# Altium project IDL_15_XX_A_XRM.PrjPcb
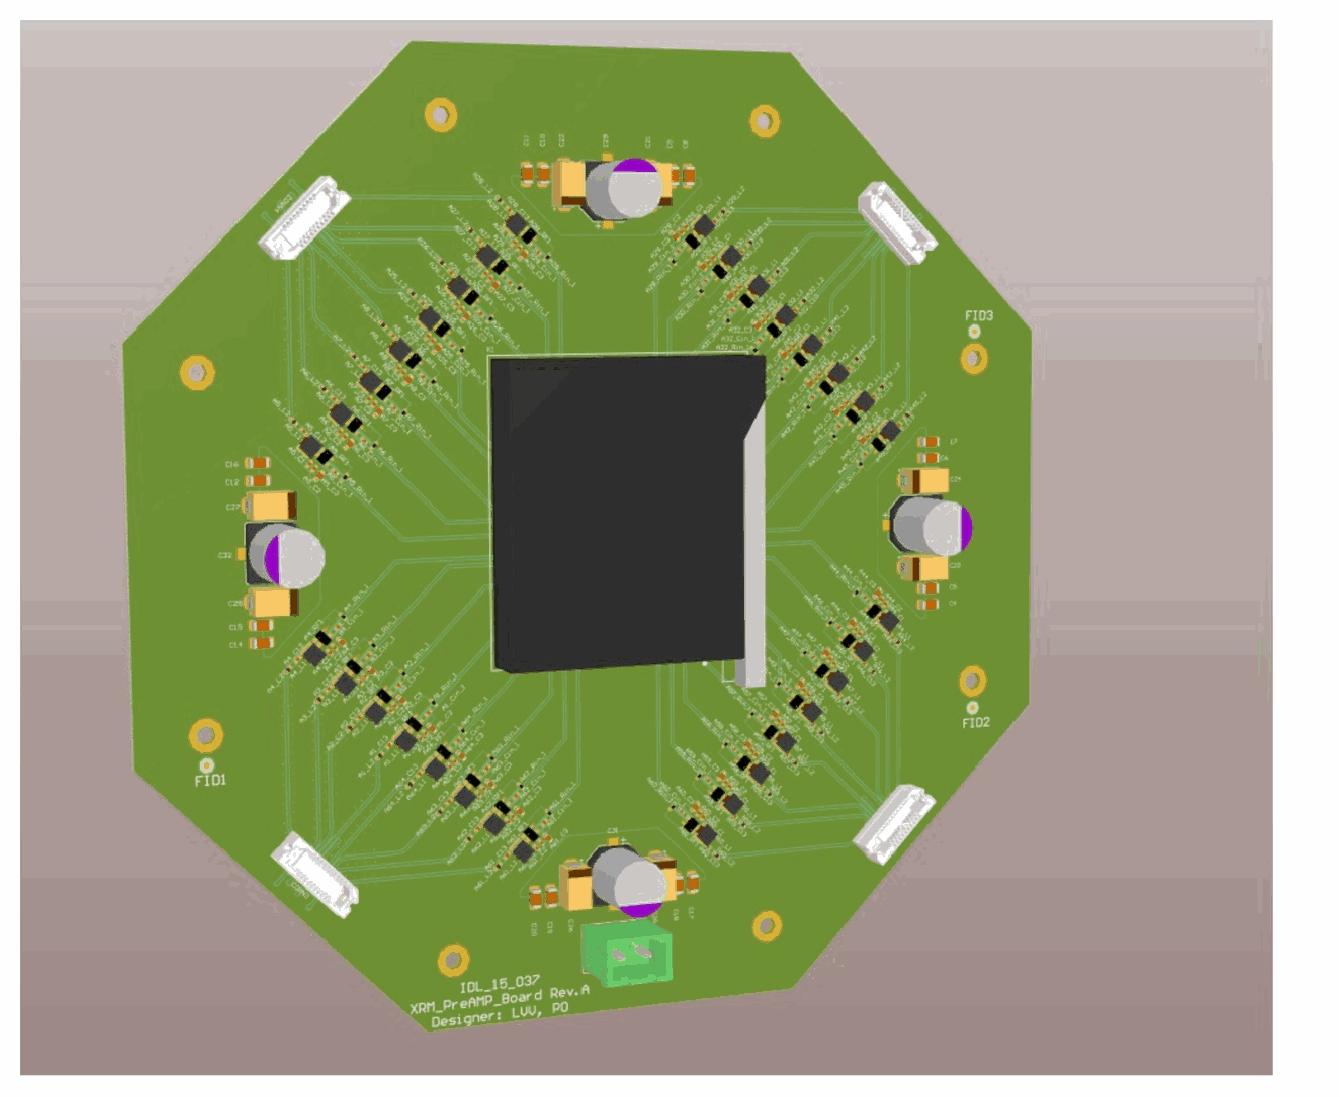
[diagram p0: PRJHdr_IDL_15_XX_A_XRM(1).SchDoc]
RevNum: A; ProjectName1: X-Ray Monitor; IDLnum: IDL_15_037; Drawn_By: Vihtori Virta; Designer: L.V. Virta, P. Orel; BoardName: XRM-Preamp Board; Approved_By: Gary S. Varner
6 sheets, 613 parts. Net scope: hierarchical (ports join the sheet entries above them; power ports are global).
Board file: IDL_15_XX_A_XRM.PcbDoc
Sheets:
  PRJHdr_IDL_15_XX_A_XRM(1).SchDoc
  IDL_15_XX_A_XRM(2).SchDoc
  IDL_15_XX_A_XRM-TOP(1).SchDoc
    A1 = IDL_15_XX_A_XRM(4).SchDoc
    A2 = IDL_15_XX_A_XRM(4).SchDoc
    A3 = IDL_15_XX_A_XRM(4).SchDoc
    A4 = IDL_15_XX_A_XRM(4).SchDoc
    A5 = IDL_15_XX_A_XRM(4).SchDoc
    A6 = IDL_15_XX_A_XRM(4).SchDoc
    A7 = IDL_15_XX_A_XRM(4).SchDoc
    A8 = IDL_15_XX_A_XRM(4).SchDoc
    A9 = IDL_15_XX_A_XRM(4).SchDoc
    A10 = IDL_15_XX_A_XRM(4).SchDoc
    A11 = IDL_15_XX_A_XRM(4).SchDoc
    A12 = IDL_15_XX_A_XRM(4).SchDoc
    A13 = IDL_15_XX_A_XRM(4).SchDoc
    A14 = IDL_15_XX_A_XRM(4).SchDoc
    A15 = IDL_15_XX_A_XRM(4).SchDoc
    A16 = IDL_15_XX_A_XRM(4).SchDoc
    A17 = IDL_15_XX_A_XRM(4).SchDoc
    A18 = IDL_15_XX_A_XRM(4).SchDoc
    A19 = IDL_15_XX_A_XRM(4).SchDoc
    A20 = IDL_15_XX_A_XRM(4).SchDoc
    A21 = IDL_15_XX_A_XRM(4).SchDoc
    A22 = IDL_15_XX_A_XRM(4).SchDoc
    A23 = IDL_15_XX_A_XRM(4).SchDoc
    A24 = IDL_15_XX_A_XRM(4).SchDoc
    A25 = IDL_15_XX_A_XRM(4).SchDoc
    A26 = IDL_15_XX_A_XRM(4).SchDoc
    A27 = IDL_15_XX_A_XRM(4).SchDoc
    A28 = IDL_15_XX_A_XRM(4).SchDoc
    A29 = IDL_15_XX_A_XRM(4).SchDoc
    A30 = IDL_15_XX_A_XRM(4).SchDoc
    A31 = IDL_15_XX_A_XRM(4).SchDoc
    A32 = IDL_15_XX_A_XRM(4).SchDoc
    A33 = IDL_15_XX_A_XRM(4).SchDoc
    A34 = IDL_15_XX_A_XRM(4).SchDoc
    A35 = IDL_15_XX_A_XRM(4).SchDoc
    A36 = IDL_15_XX_A_XRM(4).SchDoc
    A37 = IDL_15_XX_A_XRM(4).SchDoc
    A38 = IDL_15_XX_A_XRM(4).SchDoc
    A39 = IDL_15_XX_A_XRM(4).SchDoc
    A40 = IDL_15_XX_A_XRM(4).SchDoc
    A41 = IDL_15_XX_A_XRM(4).SchDoc
    A42 = IDL_15_XX_A_XRM(4).SchDoc
    A43 = IDL_15_XX_A_XRM(4).SchDoc
    A44 = IDL_15_XX_A_XRM(4).SchDoc
    A45 = IDL_15_XX_A_XRM(4).SchDoc
    A46 = IDL_15_XX_A_XRM(4).SchDoc
    A47 = IDL_15_XX_A_XRM(4).SchDoc
    A48 = IDL_15_XX_A_XRM(4).SchDoc
    A49 = IDL_15_XX_A_XRM(4).SchDoc
    A50 = IDL_15_XX_A_XRM(4).SchDoc
    A51 = IDL_15_XX_A_XRM(4).SchDoc
    A52 = IDL_15_XX_A_XRM(4).SchDoc
    A53 = IDL_15_XX_A_XRM(4).SchDoc
    A54 = IDL_15_XX_A_XRM(4).SchDoc
    A55 = IDL_15_XX_A_XRM(4).SchDoc
    A56 = IDL_15_XX_A_XRM(4).SchDoc
    A57 = IDL_15_XX_A_XRM(4).SchDoc
    A58 = IDL_15_XX_A_XRM(4).SchDoc
    A59 = IDL_15_XX_A_XRM(4).SchDoc
    A60 = IDL_15_XX_A_XRM(4).SchDoc
    A61 = IDL_15_XX_A_XRM(4).SchDoc
    A62 = IDL_15_XX_A_XRM(4).SchDoc
    A63 = IDL_15_XX_A_XRM(4).SchDoc
    A64 = IDL_15_XX_A_XRM(4).SchDoc
    U_IDL_15_XX_A_XRM-20_PIN_CONNECTOR = IDL_15_XX_A_XRM-20_PIN_CONNECTOR.SchDoc
    U_IDL_15_XX_A_XRM(3) = IDL_15_XX_A_XRM(3).SchDoc

## Sheet PRJHdr_IDL_15_XX_A_XRM(1).SchDoc: Document Header
size 401 x 291 mm; DocumentNumber: 1; SheetNumber: 1; SheetTotal: 6; Project_IT-Code: XXXX

## Sheet IDL_15_XX_A_XRM(2).SchDoc: Block Diagram
size 401 x 291 mm; DocumentNumber: 2; SheetNumber: 2; SheetTotal: 6
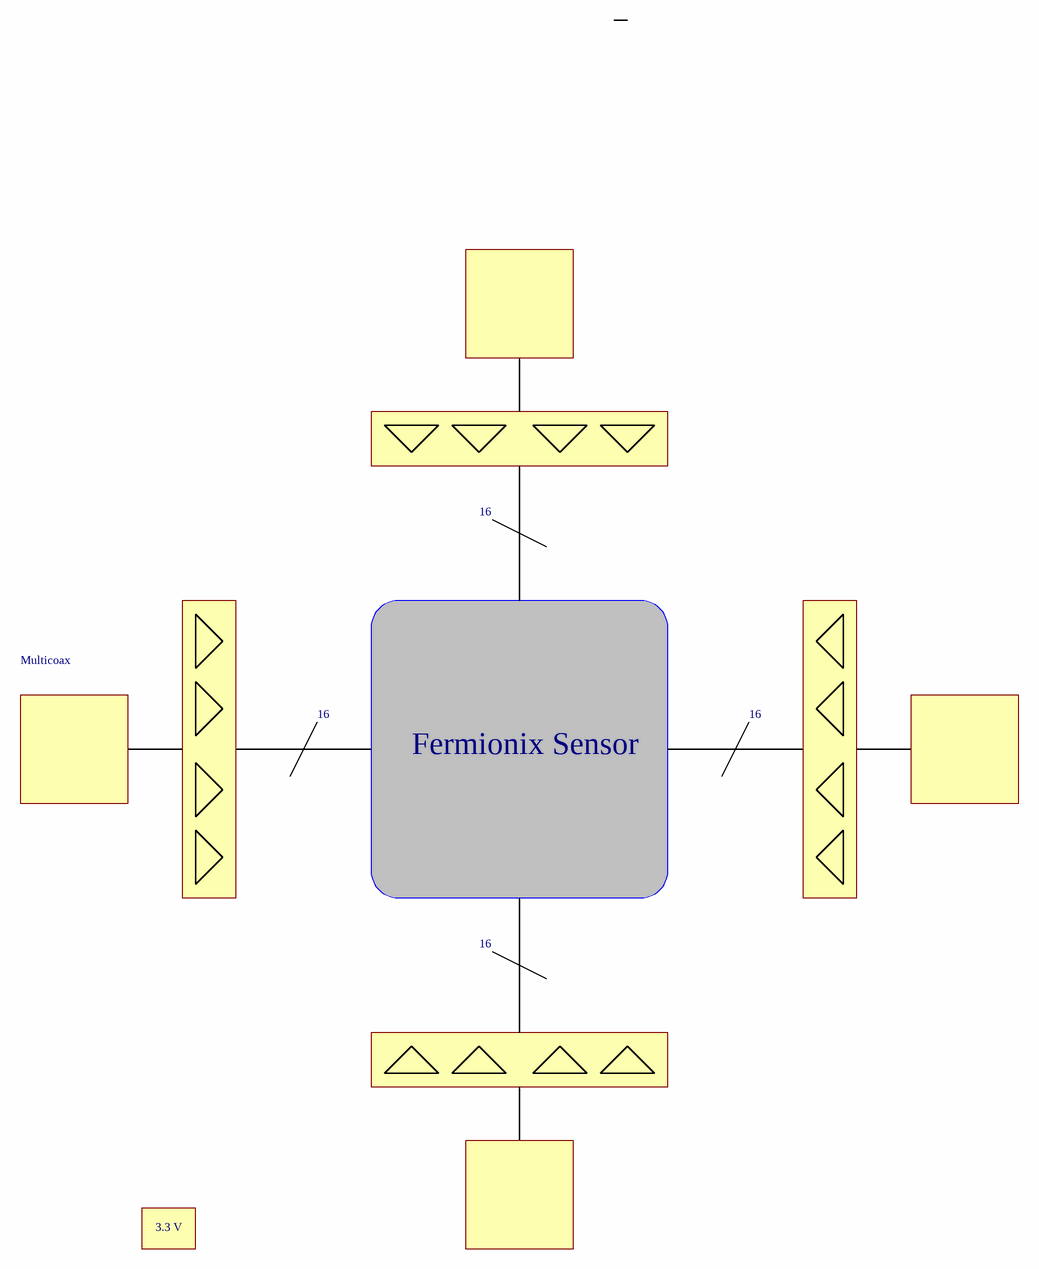
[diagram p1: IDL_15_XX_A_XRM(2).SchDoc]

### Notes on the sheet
- 16
- Multicoax
- Fermionix Sensor
- 3.3 V

## Sheet IDL_15_XX_A_XRM-TOP(1).SchDoc: Schematic - TOP
size 401 x 291 mm; DocumentNumber: 4; SheetNumber: 4; SheetTotal: 6
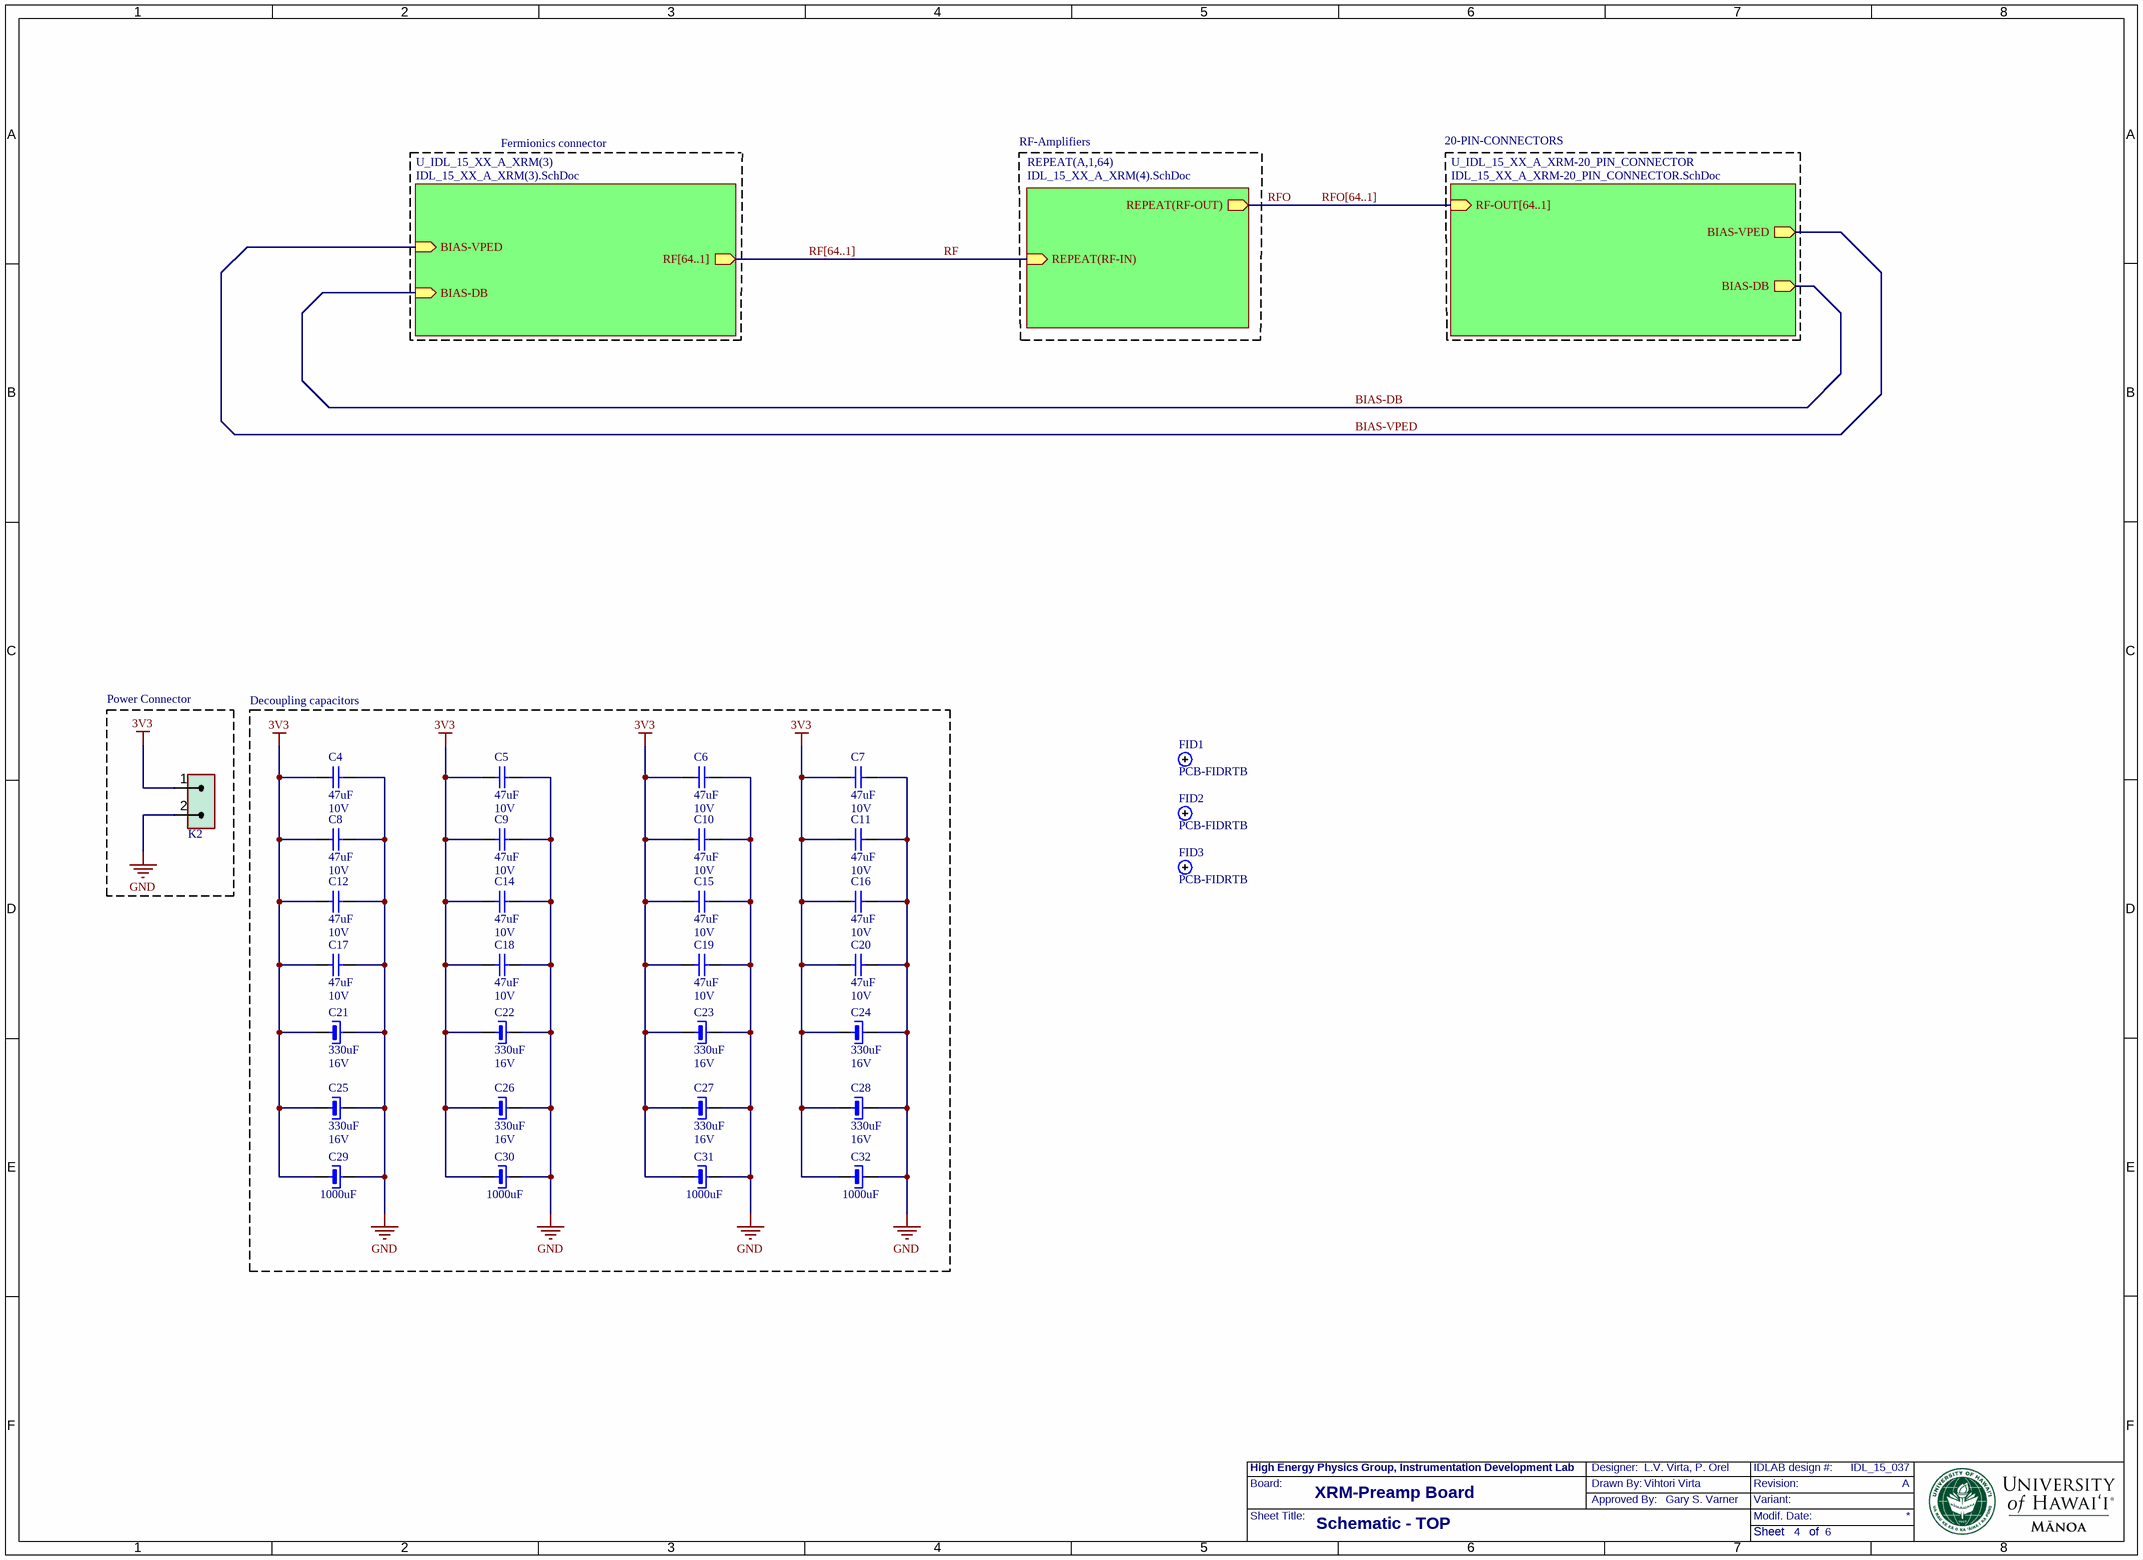
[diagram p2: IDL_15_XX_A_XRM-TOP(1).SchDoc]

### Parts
C4  47uF  Voltage rating: 10V  [CC1206N1R]
C5  47uF  Voltage rating: 10V  [CC1206N1R]
C6  47uF  Voltage rating: 10V  [CC1206N1R]
C7  47uF  Voltage rating: 10V  [CC1206N1R]
C8  47uF  Voltage rating: 10V  [CC1206N1R]
C9  47uF  Voltage rating: 10V  [CC1206N1R]
C10  47uF  Voltage rating: 10V  [CC1206N1R]
C11  47uF  Voltage rating: 10V  [CC1206N1R]
C12  47uF  Voltage rating: 10V  [CC1206N1R]
C14  47uF  Voltage rating: 10V  [CC1206N1R]
C15  47uF  Voltage rating: 10V  [CC1206N1R]
C16  47uF  Voltage rating: 10V  [CC1206N1R]
C17  47uF  Voltage rating: 10V  [CC1206N1R]
C18  47uF  Voltage rating: 10V  [CC1206N1R]
C19  47uF  Voltage rating: 10V  [CC1206N1R]
C20  47uF  Voltage rating: 10V  [CC1206N1R]
C21  330uF  Voltage rating: 16V  [CTC-D7343-43]
C22  330uF  Voltage rating: 16V  [CTC-D7343-43]
C23  330uF  Voltage rating: 16V  [CTC-D7343-43]
C24  330uF  Voltage rating: 16V  [CTC-D7343-43]
C25  330uF  Voltage rating: 16V  [CTC-D7343-43]
C26  330uF  Voltage rating: 16V  [CTC-D7343-43]
C27  330uF  Voltage rating: 16V  [CTC-D7343-43]
C28  330uF  Voltage rating: 16V  [CTC-D7343-43]
C29  1000uF  [CAPPS-D10X12.6]
C30  1000uF  [CAPPS-D10X12.6]
C31  1000uF  [CAPPS-D10X12.6]
C32  1000uF  [CAPPS-D10X12.6]
FID1  PCB-FIDRTB  [FIDRTB50]  (net tie)
FID2  PCB-FIDRTB  [FIDRTB50]  (net tie)
FID3  PCB-FIDRTB  [FIDRTB50]  (net tie)
K2  MSTBA2R5.08V  [CN_PHOENIX_MSTBVA2,5/2-G-5,08]  (value not drawn)

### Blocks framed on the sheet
Power Connector: K2
Decoupling capacitors: C4-C12 C14-C32

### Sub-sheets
REPEAT(A,1,64) = IDL_15_XX_A_XRM(4).SchDoc: REPEAT(RF-OUT) (out), REPEAT(RF-IN) (in)
U_IDL_15_XX_A_XRM(3) = IDL_15_XX_A_XRM(3).SchDoc: RF[64..1] (out), BIAS-VPED (in), BIAS-DB (in)
U_IDL_15_XX_A_XRM-20_PIN_CONNECTOR = IDL_15_XX_A_XRM-20_PIN_CONNECTOR.SchDoc: RF-OUT[64..1] (in), BIAS-VPED, BIAS-DB

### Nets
3V3: C4.1 C5.1 C6.1 C7.1 C8.1 C9.1 C10.1 C11.1 C12.1 C14.1 C15.1 C16.1 C17.1 C18.1 C19.1 C20.1 C21.1 C22.1 C23.1 C24.1 C25.1 C26.1 C27.1 C28.1 C29.1 C30.1 C31.1 C32.1 K2.1
GND: C4.2 C5.2 C6.2 C7.2 C8.2 C9.2 C10.2 C11.2 C12.2 C14.2 C15.2 C16.2 C17.2 C18.2 C19.2 C20.2 C21.2 C22.2 C23.2 C24.2 C25.2 C26.2 C27.2 C28.2 C29.2 C30.2 C31.2 C32.2 K2.2
BIAS-DB: sheet U_IDL_15_XX_A_XRM-20_PIN_CONNECTOR/BIAS-DB, sheet U_IDL_15_XX_A_XRM(3)/BIAS-DB
BIAS-VPED: sheet U_IDL_15_XX_A_XRM-20_PIN_CONNECTOR/BIAS-VPED, sheet U_IDL_15_XX_A_XRM(3)/BIAS-VPED  [project net BIAS-DB]

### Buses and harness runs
bus RF[64..1] = sheet U_IDL_15_XX_A_XRM(3)/RF[64..1]
bus RFO[64..1] = sheet U_IDL_15_XX_A_XRM-20_PIN_CONNECTOR/RF-OUT[64..1]

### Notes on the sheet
- Fermionics connector
- RF-Amplifiers
- 20-PIN-CONNECTORS

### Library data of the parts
C4-C12 C14-C20 = CAPCC1206_47U_10VX5R: Capacitor chip ceramic 1206 10V X5R; Manufacturer: Murata; Manufacturer No: GRM31CR61A476ME15L; Tech: SMDR
C21-C28 = CAPT7343_330U_16V: Capacitor tantal smd 7343-43 16V 50mResr; Manufacturer: Kemet; Manufacturer No: T521X337M016ATE050; Tech: SMDR
C29-C32 = CAPPS1000U-16V80mR: Capacitor electrolitic SMD 10x10x8mm 16V 80mR; Manufacturer: Panasonic; Manufacturer No: EEE-FT1C102AP; Tech: SMDR
FID1-FID3 = PCB-FIDRTB: Fiducial top & bottom round open mask; Sort: 800; Tech: MECH
K2 = CN_MSTBA2R5.08V: Combicon header 2 pin vertical closed R5.08mm 12A 300V; Manufacturer: Phoenix Contact; Manufacturer No: 1755736; Tech: THDW

## Sheet IDL_15_XX_A_XRM(4).SchDoc: Schematic - Amplifier connections
size 401 x 291 mm; DocumentNumber: 5; SheetNumber: 5; SheetTotal: 6
Used 64 times, as channels A1, A2, A3, A4, A5, A6, A7, A8, A9, A10, A11, A12, A13, A14, A15, A16, A17, A18, A19, A20, A21, A22, A23, A24, A25, A26, A27, A28, A29, A30, A31, A32, A33, A34, A35, A36, A37, A38, A39, A40, A41, A42, A43, A44, A45, A46, A47, A48, A49, A50, A51, A52, A53, A54, A55, A56, A57, A58, A59, A60, A61, A62, A63, A64. Parts and nets are listed once, with the designators drawn on the sheet.
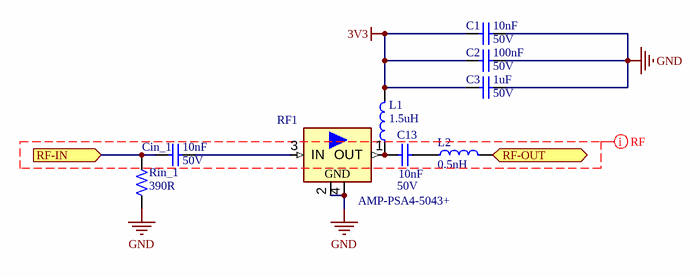
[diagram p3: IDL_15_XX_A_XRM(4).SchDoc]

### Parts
C1  10nF  Voltage rating: 50V  [CC0402N1R]
C2  100nF  Voltage rating: 50V  [CC0402N1R]
C3  1uF  Voltage rating: 50V  [CC0603RF1R]
C13  10nF  Voltage rating: 50V  [CC0402N1R]
Cin_1  10nF  Voltage rating: 50V  [CC0402N1R]
L1  1.5uH  [LC1008CS]
L2  0.5nH  [LC0402N1R]
RF1  AMP-PSA4-5043+  [MMM1362]
Rin_1  390R  [RC0402N1R]

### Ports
RF-IN (in), RF-OUT (out)

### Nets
3V3: C1.1 C2.1 C3.1 L1.2
GND: C1.2 C2.2 C3.2 RF1.2(GND) RF1.4(GND) Rin_1.1
RF-IN: Cin_1.1 Rin_1.2 ; port RF-IN
RF-OUT: L2.2 ; port RF-OUT
NetC13_1: C13.1 L1.1 RF1.1(OUT)
NetC13_2: C13.2 L2.1
NetCin_1_2: Cin_1.2 RF1.3(IN)

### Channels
A1: designators C1=A1_C1 C2=A1_C2 C3=A1_C3 C13=A1_C13 Cin_1=A1_Cin_1 L1=A1_L1 L2=A1_L2 RF1=A1_RF1 Rin_1=A1_Rin_1; ports RF-IN=RF1 RF-OUT=RF-OUT1
A2: designators C1=A2_C1 C2=A2_C2 C3=A2_C3 C13=A2_C13 Cin_1=A2_Cin_1 L1=A2_L1 L2=A2_L2 RF1=A2_RF1 Rin_1=A2_Rin_1; ports RF-IN=RF2 RF-OUT=RF-OUT2
A3: designators C1=A3_C1 C2=A3_C2 C3=A3_C3 C13=A3_C13 Cin_1=A3_Cin_1 L1=A3_L1 L2=A3_L2 RF1=A3_RF1 Rin_1=A3_Rin_1; ports RF-IN=RF3 RF-OUT=RF-OUT3
A4: designators C1=A4_C1 C2=A4_C2 C3=A4_C3 C13=A4_C13 Cin_1=A4_Cin_1 L1=A4_L1 L2=A4_L2 RF1=A4_RF1 Rin_1=A4_Rin_1; ports RF-IN=RF4 RF-OUT=RF-OUT4
A5: designators C1=A5_C1 C2=A5_C2 C3=A5_C3 C13=A5_C13 Cin_1=A5_Cin_1 L1=A5_L1 L2=A5_L2 RF1=A5_RF1 Rin_1=A5_Rin_1; ports RF-IN=RF5 RF-OUT=RF-OUT5
A6: designators C1=A6_C1 C2=A6_C2 C3=A6_C3 C13=A6_C13 Cin_1=A6_Cin_1 L1=A6_L1 L2=A6_L2 RF1=A6_RF1 Rin_1=A6_Rin_1; ports RF-IN=RF6 RF-OUT=RF-OUT6
A7: designators C1=A7_C1 C2=A7_C2 C3=A7_C3 C13=A7_C13 Cin_1=A7_Cin_1 L1=A7_L1 L2=A7_L2 RF1=A7_RF1 Rin_1=A7_Rin_1; ports RF-IN=RF7 RF-OUT=RF-OUT7
A8: designators C1=A8_C1 C2=A8_C2 C3=A8_C3 C13=A8_C13 Cin_1=A8_Cin_1 L1=A8_L1 L2=A8_L2 RF1=A8_RF1 Rin_1=A8_Rin_1; ports RF-IN=RF8 RF-OUT=RF-OUT8
A9: designators C1=A9_C1 C2=A9_C2 C3=A9_C3 C13=A9_C13 Cin_1=A9_Cin_1 L1=A9_L1 L2=A9_L2 RF1=A9_RF1 Rin_1=A9_Rin_1; ports RF-IN=RF9 RF-OUT=RF-OUT9
A10: designators C1=A10_C1 C2=A10_C2 C3=A10_C3 C13=A10_C13 Cin_1=A10_Cin_1 L1=A10_L1 L2=A10_L2 RF1=A10_RF1 Rin_1=A10_Rin_1; ports RF-IN=RF10 RF-OUT=RF-OUT10
A11: designators C1=A11_C1 C2=A11_C2 C3=A11_C3 C13=A11_C13 Cin_1=A11_Cin_1 L1=A11_L1 L2=A11_L2 RF1=A11_RF1 Rin_1=A11_Rin_1; ports RF-IN=RF11 RF-OUT=RF-OUT11
A12: designators C1=A12_C1 C2=A12_C2 C3=A12_C3 C13=A12_C13 Cin_1=A12_Cin_1 L1=A12_L1 L2=A12_L2 RF1=A12_RF1 Rin_1=A12_Rin_1; ports RF-IN=RF12 RF-OUT=RF-OUT12
A13: designators C1=A13_C1 C2=A13_C2 C3=A13_C3 C13=A13_C13 Cin_1=A13_Cin_1 L1=A13_L1 L2=A13_L2 RF1=A13_RF1 Rin_1=A13_Rin_1; ports RF-IN=RF13 RF-OUT=RF-OUT13
A14: designators C1=A14_C1 C2=A14_C2 C3=A14_C3 C13=A14_C13 Cin_1=A14_Cin_1 L1=A14_L1 L2=A14_L2 RF1=A14_RF1 Rin_1=A14_Rin_1; ports RF-IN=RF14 RF-OUT=RF-OUT14
A15: designators C1=A15_C1 C2=A15_C2 C3=A15_C3 C13=A15_C13 Cin_1=A15_Cin_1 L1=A15_L1 L2=A15_L2 RF1=A15_RF1 Rin_1=A15_Rin_1; ports RF-IN=RF15 RF-OUT=RF-OUT15
A16: designators C1=A16_C1 C2=A16_C2 C3=A16_C3 C13=A16_C13 Cin_1=A16_Cin_1 L1=A16_L1 L2=A16_L2 RF1=A16_RF1 Rin_1=A16_Rin_1; ports RF-IN=RF16 RF-OUT=RF-OUT16
A17: designators C1=A17_C1 C2=A17_C2 C3=A17_C3 C13=A17_C13 Cin_1=A17_Cin_1 L1=A17_L1 L2=A17_L2 RF1=A17_RF1 Rin_1=A17_Rin_1; ports RF-IN=RF17 RF-OUT=RF-OUT17
A18: designators C1=A18_C1 C2=A18_C2 C3=A18_C3 C13=A18_C13 Cin_1=A18_Cin_1 L1=A18_L1 L2=A18_L2 RF1=A18_RF1 Rin_1=A18_Rin_1; ports RF-IN=RF18 RF-OUT=RF-OUT18
A19: designators C1=A19_C1 C2=A19_C2 C3=A19_C3 C13=A19_C13 Cin_1=A19_Cin_1 L1=A19_L1 L2=A19_L2 RF1=A19_RF1 Rin_1=A19_Rin_1; ports RF-IN=RF19 RF-OUT=RF-OUT19
A20: designators C1=A20_C1 C2=A20_C2 C3=A20_C3 C13=A20_C13 Cin_1=A20_Cin_1 L1=A20_L1 L2=A20_L2 RF1=A20_RF1 Rin_1=A20_Rin_1; ports RF-IN=RF20 RF-OUT=RF-OUT20
A21: designators C1=A21_C1 C2=A21_C2 C3=A21_C3 C13=A21_C13 Cin_1=A21_Cin_1 L1=A21_L1 L2=A21_L2 RF1=A21_RF1 Rin_1=A21_Rin_1; ports RF-IN=RF21 RF-OUT=RF-OUT21
A22: designators C1=A22_C1 C2=A22_C2 C3=A22_C3 C13=A22_C13 Cin_1=A22_Cin_1 L1=A22_L1 L2=A22_L2 RF1=A22_RF1 Rin_1=A22_Rin_1; ports RF-IN=RF22 RF-OUT=RF-OUT22
A23: designators C1=A23_C1 C2=A23_C2 C3=A23_C3 C13=A23_C13 Cin_1=A23_Cin_1 L1=A23_L1 L2=A23_L2 RF1=A23_RF1 Rin_1=A23_Rin_1; ports RF-IN=RF23 RF-OUT=RF-OUT23
A24: designators C1=A24_C1 C2=A24_C2 C3=A24_C3 C13=A24_C13 Cin_1=A24_Cin_1 L1=A24_L1 L2=A24_L2 RF1=A24_RF1 Rin_1=A24_Rin_1; ports RF-IN=RF24 RF-OUT=RF-OUT24
A25: designators C1=A25_C1 C2=A25_C2 C3=A25_C3 C13=A25_C13 Cin_1=A25_Cin_1 L1=A25_L1 L2=A25_L2 RF1=A25_RF1 Rin_1=A25_Rin_1; ports RF-IN=RF25 RF-OUT=RF-OUT25
A26: designators C1=A26_C1 C2=A26_C2 C3=A26_C3 C13=A26_C13 Cin_1=A26_Cin_1 L1=A26_L1 L2=A26_L2 RF1=A26_RF1 Rin_1=A26_Rin_1; ports RF-IN=RF26 RF-OUT=RF-OUT26
A27: designators C1=A27_C1 C2=A27_C2 C3=A27_C3 C13=A27_C13 Cin_1=A27_Cin_1 L1=A27_L1 L2=A27_L2 RF1=A27_RF1 Rin_1=A27_Rin_1; ports RF-IN=RF27 RF-OUT=RF-OUT27
A28: designators C1=A28_C1 C2=A28_C2 C3=A28_C3 C13=A28_C13 Cin_1=A28_Cin_1 L1=A28_L1 L2=A28_L2 RF1=A28_RF1 Rin_1=A28_Rin_1; ports RF-IN=RF28 RF-OUT=RF-OUT28
A29: designators C1=A29_C1 C2=A29_C2 C3=A29_C3 C13=A29_C13 Cin_1=A29_Cin_1 L1=A29_L1 L2=A29_L2 RF1=A29_RF1 Rin_1=A29_Rin_1; ports RF-IN=RF29 RF-OUT=RF-OUT29
A30: designators C1=A30_C1 C2=A30_C2 C3=A30_C3 C13=A30_C13 Cin_1=A30_Cin_1 L1=A30_L1 L2=A30_L2 RF1=A30_RF1 Rin_1=A30_Rin_1; ports RF-IN=RF30 RF-OUT=RF-OUT30
A31: designators C1=A31_C1 C2=A31_C2 C3=A31_C3 C13=A31_C13 Cin_1=A31_Cin_1 L1=A31_L1 L2=A31_L2 RF1=A31_RF1 Rin_1=A31_Rin_1; ports RF-IN=RF31 RF-OUT=RF-OUT31
A32: designators C1=A32_C1 C2=A32_C2 C3=A32_C3 C13=A32_C13 Cin_1=A32_Cin_1 L1=A32_L1 L2=A32_L2 RF1=A32_RF1 Rin_1=A32_Rin_1; ports RF-IN=RF32 RF-OUT=RF-OUT32
A33: designators C1=A33_C1 C2=A33_C2 C3=A33_C3 C13=A33_C13 Cin_1=A33_Cin_1 L1=A33_L1 L2=A33_L2 RF1=A33_RF1 Rin_1=A33_Rin_1; ports RF-IN=RF33 RF-OUT=RF-OUT33
A34: designators C1=A34_C1 C2=A34_C2 C3=A34_C3 C13=A34_C13 Cin_1=A34_Cin_1 L1=A34_L1 L2=A34_L2 RF1=A34_RF1 Rin_1=A34_Rin_1; ports RF-IN=RF34 RF-OUT=RF-OUT34
A35: designators C1=A35_C1 C2=A35_C2 C3=A35_C3 C13=A35_C13 Cin_1=A35_Cin_1 L1=A35_L1 L2=A35_L2 RF1=A35_RF1 Rin_1=A35_Rin_1; ports RF-IN=RF35 RF-OUT=RF-OUT35
A36: designators C1=A36_C1 C2=A36_C2 C3=A36_C3 C13=A36_C13 Cin_1=A36_Cin_1 L1=A36_L1 L2=A36_L2 RF1=A36_RF1 Rin_1=A36_Rin_1; ports RF-IN=RF36 RF-OUT=RF-OUT36
A37: designators C1=A37_C1 C2=A37_C2 C3=A37_C3 C13=A37_C13 Cin_1=A37_Cin_1 L1=A37_L1 L2=A37_L2 RF1=A37_RF1 Rin_1=A37_Rin_1; ports RF-IN=RF37 RF-OUT=RF-OUT37
A38: designators C1=A38_C1 C2=A38_C2 C3=A38_C3 C13=A38_C13 Cin_1=A38_Cin_1 L1=A38_L1 L2=A38_L2 RF1=A38_RF1 Rin_1=A38_Rin_1; ports RF-IN=RF38 RF-OUT=RF-OUT38
A39: designators C1=A39_C1 C2=A39_C2 C3=A39_C3 C13=A39_C13 Cin_1=A39_Cin_1 L1=A39_L1 L2=A39_L2 RF1=A39_RF1 Rin_1=A39_Rin_1; ports RF-IN=RF39 RF-OUT=RF-OUT39
A40: designators C1=A40_C1 C2=A40_C2 C3=A40_C3 C13=A40_C13 Cin_1=A40_Cin_1 L1=A40_L1 L2=A40_L2 RF1=A40_RF1 Rin_1=A40_Rin_1; ports RF-IN=RF40 RF-OUT=RF-OUT40
A41: designators C1=A41_C1 C2=A41_C2 C3=A41_C3 C13=A41_C13 Cin_1=A41_Cin_1 L1=A41_L1 L2=A41_L2 RF1=A41_RF1 Rin_1=A41_Rin_1; ports RF-IN=RF41 RF-OUT=RF-OUT41
A42: designators C1=A42_C1 C2=A42_C2 C3=A42_C3 C13=A42_C13 Cin_1=A42_Cin_1 L1=A42_L1 L2=A42_L2 RF1=A42_RF1 Rin_1=A42_Rin_1; ports RF-IN=RF42 RF-OUT=RF-OUT42
A43: designators C1=A43_C1 C2=A43_C2 C3=A43_C3 C13=A43_C13 Cin_1=A43_Cin_1 L1=A43_L1 L2=A43_L2 RF1=A43_RF1 Rin_1=A43_Rin_1; ports RF-IN=RF43 RF-OUT=RF-OUT43
A44: designators C1=A44_C1 C2=A44_C2 C3=A44_C3 C13=A44_C13 Cin_1=A44_Cin_1 L1=A44_L1 L2=A44_L2 RF1=A44_RF1 Rin_1=A44_Rin_1; ports RF-IN=RF44 RF-OUT=RF-OUT44
A45: designators C1=A45_C1 C2=A45_C2 C3=A45_C3 C13=A45_C13 Cin_1=A45_Cin_1 L1=A45_L1 L2=A45_L2 RF1=A45_RF1 Rin_1=A45_Rin_1; ports RF-IN=RF45 RF-OUT=RF-OUT45
A46: designators C1=A46_C1 C2=A46_C2 C3=A46_C3 C13=A46_C13 Cin_1=A46_Cin_1 L1=A46_L1 L2=A46_L2 RF1=A46_RF1 Rin_1=A46_Rin_1; ports RF-IN=RF46 RF-OUT=RF-OUT46
A47: designators C1=A47_C1 C2=A47_C2 C3=A47_C3 C13=A47_C13 Cin_1=A47_Cin_1 L1=A47_L1 L2=A47_L2 RF1=A47_RF1 Rin_1=A47_Rin_1; ports RF-IN=RF47 RF-OUT=RF-OUT47
A48: designators C1=A48_C1 C2=A48_C2 C3=A48_C3 C13=A48_C13 Cin_1=A48_Cin_1 L1=A48_L1 L2=A48_L2 RF1=A48_RF1 Rin_1=A48_Rin_1; ports RF-IN=RF48 RF-OUT=RF-OUT48
A49: designators C1=A49_C1 C2=A49_C2 C3=A49_C3 C13=A49_C13 Cin_1=A49_Cin_1 L1=A49_L1 L2=A49_L2 RF1=A49_RF1 Rin_1=A49_Rin_1; ports RF-IN=RF49 RF-OUT=RF-OUT49
A50: designators C1=A50_C1 C2=A50_C2 C3=A50_C3 C13=A50_C13 Cin_1=A50_Cin_1 L1=A50_L1 L2=A50_L2 RF1=A50_RF1 Rin_1=A50_Rin_1; ports RF-IN=RF50 RF-OUT=RF-OUT50
A51: designators C1=A51_C1 C2=A51_C2 C3=A51_C3 C13=A51_C13 Cin_1=A51_Cin_1 L1=A51_L1 L2=A51_L2 RF1=A51_RF1 Rin_1=A51_Rin_1; ports RF-IN=RF51 RF-OUT=RF-OUT51
A52: designators C1=A52_C1 C2=A52_C2 C3=A52_C3 C13=A52_C13 Cin_1=A52_Cin_1 L1=A52_L1 L2=A52_L2 RF1=A52_RF1 Rin_1=A52_Rin_1; ports RF-IN=RF52 RF-OUT=RF-OUT52
A53: designators C1=A53_C1 C2=A53_C2 C3=A53_C3 C13=A53_C13 Cin_1=A53_Cin_1 L1=A53_L1 L2=A53_L2 RF1=A53_RF1 Rin_1=A53_Rin_1; ports RF-IN=RF53 RF-OUT=RF-OUT53
A54: designators C1=A54_C1 C2=A54_C2 C3=A54_C3 C13=A54_C13 Cin_1=A54_Cin_1 L1=A54_L1 L2=A54_L2 RF1=A54_RF1 Rin_1=A54_Rin_1; ports RF-IN=RF54 RF-OUT=RF-OUT54
A55: designators C1=A55_C1 C2=A55_C2 C3=A55_C3 C13=A55_C13 Cin_1=A55_Cin_1 L1=A55_L1 L2=A55_L2 RF1=A55_RF1 Rin_1=A55_Rin_1; ports RF-IN=RF55 RF-OUT=RF-OUT55
A56: designators C1=A56_C1 C2=A56_C2 C3=A56_C3 C13=A56_C13 Cin_1=A56_Cin_1 L1=A56_L1 L2=A56_L2 RF1=A56_RF1 Rin_1=A56_Rin_1; ports RF-IN=RF56 RF-OUT=RF-OUT56
A57: designators C1=A57_C1 C2=A57_C2 C3=A57_C3 C13=A57_C13 Cin_1=A57_Cin_1 L1=A57_L1 L2=A57_L2 RF1=A57_RF1 Rin_1=A57_Rin_1; ports RF-IN=RF57 RF-OUT=RF-OUT57
A58: designators C1=A58_C1 C2=A58_C2 C3=A58_C3 C13=A58_C13 Cin_1=A58_Cin_1 L1=A58_L1 L2=A58_L2 RF1=A58_RF1 Rin_1=A58_Rin_1; ports RF-IN=RF58 RF-OUT=RF-OUT58
A59: designators C1=A59_C1 C2=A59_C2 C3=A59_C3 C13=A59_C13 Cin_1=A59_Cin_1 L1=A59_L1 L2=A59_L2 RF1=A59_RF1 Rin_1=A59_Rin_1; ports RF-IN=RF59 RF-OUT=RF-OUT59
A60: designators C1=A60_C1 C2=A60_C2 C3=A60_C3 C13=A60_C13 Cin_1=A60_Cin_1 L1=A60_L1 L2=A60_L2 RF1=A60_RF1 Rin_1=A60_Rin_1; ports RF-IN=RF60 RF-OUT=RF-OUT60
A61: designators C1=A61_C1 C2=A61_C2 C3=A61_C3 C13=A61_C13 Cin_1=A61_Cin_1 L1=A61_L1 L2=A61_L2 RF1=A61_RF1 Rin_1=A61_Rin_1; ports RF-IN=RF61 RF-OUT=RF-OUT61
A62: designators C1=A62_C1 C2=A62_C2 C3=A62_C3 C13=A62_C13 Cin_1=A62_Cin_1 L1=A62_L1 L2=A62_L2 RF1=A62_RF1 Rin_1=A62_Rin_1; ports RF-IN=RF62 RF-OUT=RF-OUT62
A63: designators C1=A63_C1 C2=A63_C2 C3=A63_C3 C13=A63_C13 Cin_1=A63_Cin_1 L1=A63_L1 L2=A63_L2 RF1=A63_RF1 Rin_1=A63_Rin_1; ports RF-IN=RF63 RF-OUT=RF-OUT63
A64: designators C1=A64_C1 C2=A64_C2 C3=A64_C3 C13=A64_C13 Cin_1=A64_Cin_1 L1=A64_L1 L2=A64_L2 RF1=A64_RF1 Rin_1=A64_Rin_1; ports RF-IN=RF64 RF-OUT=RF-OUT64

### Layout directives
net class RF: (no net found under the mark)

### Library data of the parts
C1 C13 Cin_1 = CAPCC0402_1_10.0N_50VX7R: Capacitor chip ceramic 0402 50V X7R; Manufacturer: Murata; Manufacturer No: GRM155R71H103KA88D; Tech: SMDR
C2 = CAPCC0402_1_100N_50VX7R: Capacitor chip ceramic 0402 50V X7R; Manufacturer: TDK; Manufacturer No: C1005X7R1H104K050BB; Tech: SMDR
C3 = CAPCC0603_2_1U_50VX7R: Capacitor chip ceramic 0603 50V X7R; Manufacturer: Murata; Manufacturer No: GRM188R71E105KA12D; Tech: SMDR
L1 = IND1008-1.5U_0.33A: Chip inductor 1008 0.33A 2.3R; Manufacturer: Coilcraft; Manufacturer No: 1008CS-152XJLB; Tech: SMDR
L2 = IND0402-10.5N_1.0A: Chip inductor 0402 1.0A 100mR; Manufacturer: TDK; Manufacturer No: MLG1005S0N5CT000; Tech: SMDR
RF1 = AMP-PSA4-5043+: Monolithic Amplifier 50MHz - 4GHz, 0.75NF; Manufacturer: MiniCircuits; Tech: SMDR
Rin_1 = RES SMD 390 OHM 1% 1/10W 0402: Chip Resistor 0402 0.1mW 1% 100ppm; Manufacturer: Panasonic; Manufacturer No: ERJ-2RKF3900X; Tech: SMDR

## Sheet IDL_15_XX_A_XRM-20_PIN_CONNECTOR.SchDoc: Schematic - 20-pin connector
size 401 x 291 mm; DocumentNumber: 6; SheetNumber: 6; SheetTotal: 6
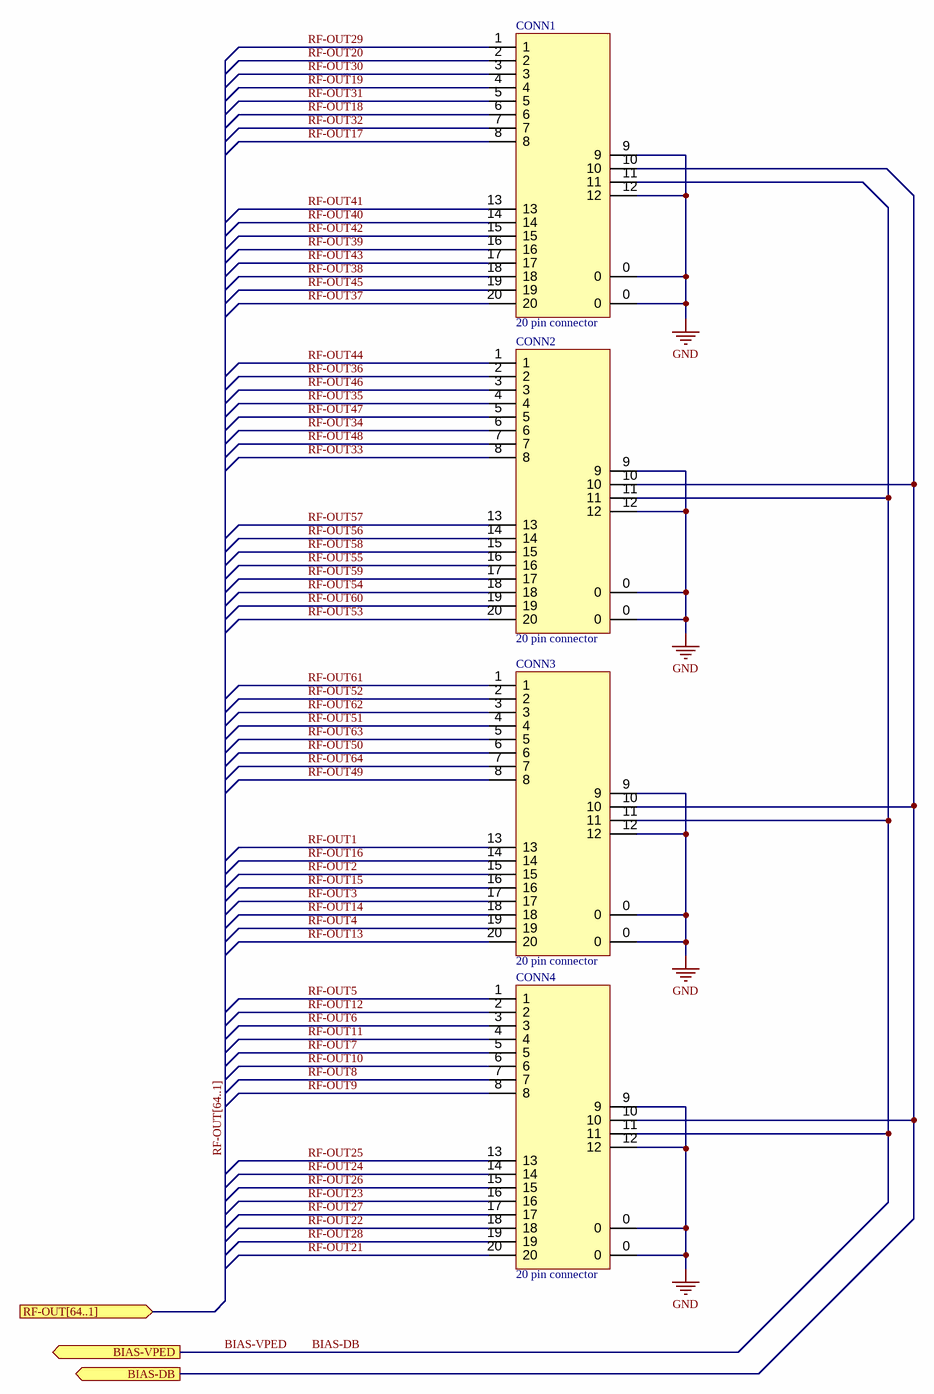
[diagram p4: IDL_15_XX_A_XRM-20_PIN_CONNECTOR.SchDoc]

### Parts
CONN1  20 pin connector  [20-pin-connector]
CONN2  20 pin connector  [20-pin-connector]
CONN3  20 pin connector  [20-pin-connector]
CONN4  20 pin connector  [20-pin-connector]

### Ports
BIAS-DB (out), BIAS-VPED (out), RF-OUT[64..1] (in)

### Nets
GND: CONN1.0 CONN1.9 CONN1.12 CONN2.0 CONN2.9 CONN2.12 CONN3.0 CONN3.9 CONN3.12 CONN4.0 CONN4.9 CONN4.12
BIAS-DB: CONN1.10 CONN2.10 CONN3.10 CONN4.10 ; port BIAS-DB
BIAS-DB: CONN1.11 CONN2.11 CONN3.11 CONN4.11 ; port BIAS-VPED  [also labelled BIAS-VPED]  [a separate net that carries the same name]
RF-OUT1: CONN3.13
RF-OUT2: CONN3.15
RF-OUT3: CONN3.17
RF-OUT4: CONN3.19
RF-OUT5: CONN4.1
RF-OUT6: CONN4.3
RF-OUT7: CONN4.5
RF-OUT8: CONN4.7
RF-OUT9: CONN4.8
RF-OUT10: CONN4.6
RF-OUT11: CONN4.4
RF-OUT12: CONN4.2
RF-OUT13: CONN3.20
RF-OUT14: CONN3.18
RF-OUT15: CONN3.16
RF-OUT16: CONN3.14
RF-OUT17: CONN1.8
RF-OUT18: CONN1.6
RF-OUT19: CONN1.4
RF-OUT20: CONN1.2
RF-OUT21: CONN4.20
RF-OUT22: CONN4.18
RF-OUT23: CONN4.16
RF-OUT24: CONN4.14
RF-OUT25: CONN4.13
RF-OUT26: CONN4.15
RF-OUT27: CONN4.17
RF-OUT28: CONN4.19
RF-OUT29: CONN1.1
RF-OUT30: CONN1.3
RF-OUT31: CONN1.5
RF-OUT32: CONN1.7
RF-OUT33: CONN2.8
RF-OUT34: CONN2.6
RF-OUT35: CONN2.4
RF-OUT36: CONN2.2
RF-OUT37: CONN1.20
RF-OUT38: CONN1.18
RF-OUT39: CONN1.16
RF-OUT40: CONN1.14
RF-OUT41: CONN1.13
RF-OUT42: CONN1.15
RF-OUT43: CONN1.17
RF-OUT44: CONN2.1
RF-OUT45: CONN1.19
RF-OUT46: CONN2.3
RF-OUT47: CONN2.5
RF-OUT48: CONN2.7
RF-OUT49: CONN3.8
RF-OUT50: CONN3.6
RF-OUT51: CONN3.4
RF-OUT52: CONN3.2
RF-OUT53: CONN2.20
RF-OUT54: CONN2.18
RF-OUT55: CONN2.16
RF-OUT56: CONN2.14
RF-OUT57: CONN2.13
RF-OUT58: CONN2.15
RF-OUT59: CONN2.17
RF-OUT60: CONN2.19
RF-OUT61: CONN3.1
RF-OUT62: CONN3.3
RF-OUT63: CONN3.5
RF-OUT64: CONN3.7

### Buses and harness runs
bus RF-OUT[64..1] = port RF-OUT[64..1]

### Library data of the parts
CONN1-CONN4 = 20 Pin Connector-Samtec-ERF8-010-05.0-L-DV-L-TR: Manufacturer: Samtec; Tech: SMDR

## Sheet IDL_15_XX_A_XRM(3).SchDoc: Schematic-Connectors
size 401 x 291 mm; DocumentNumber: 3; SheetNumber: 3; SheetTotal: 6
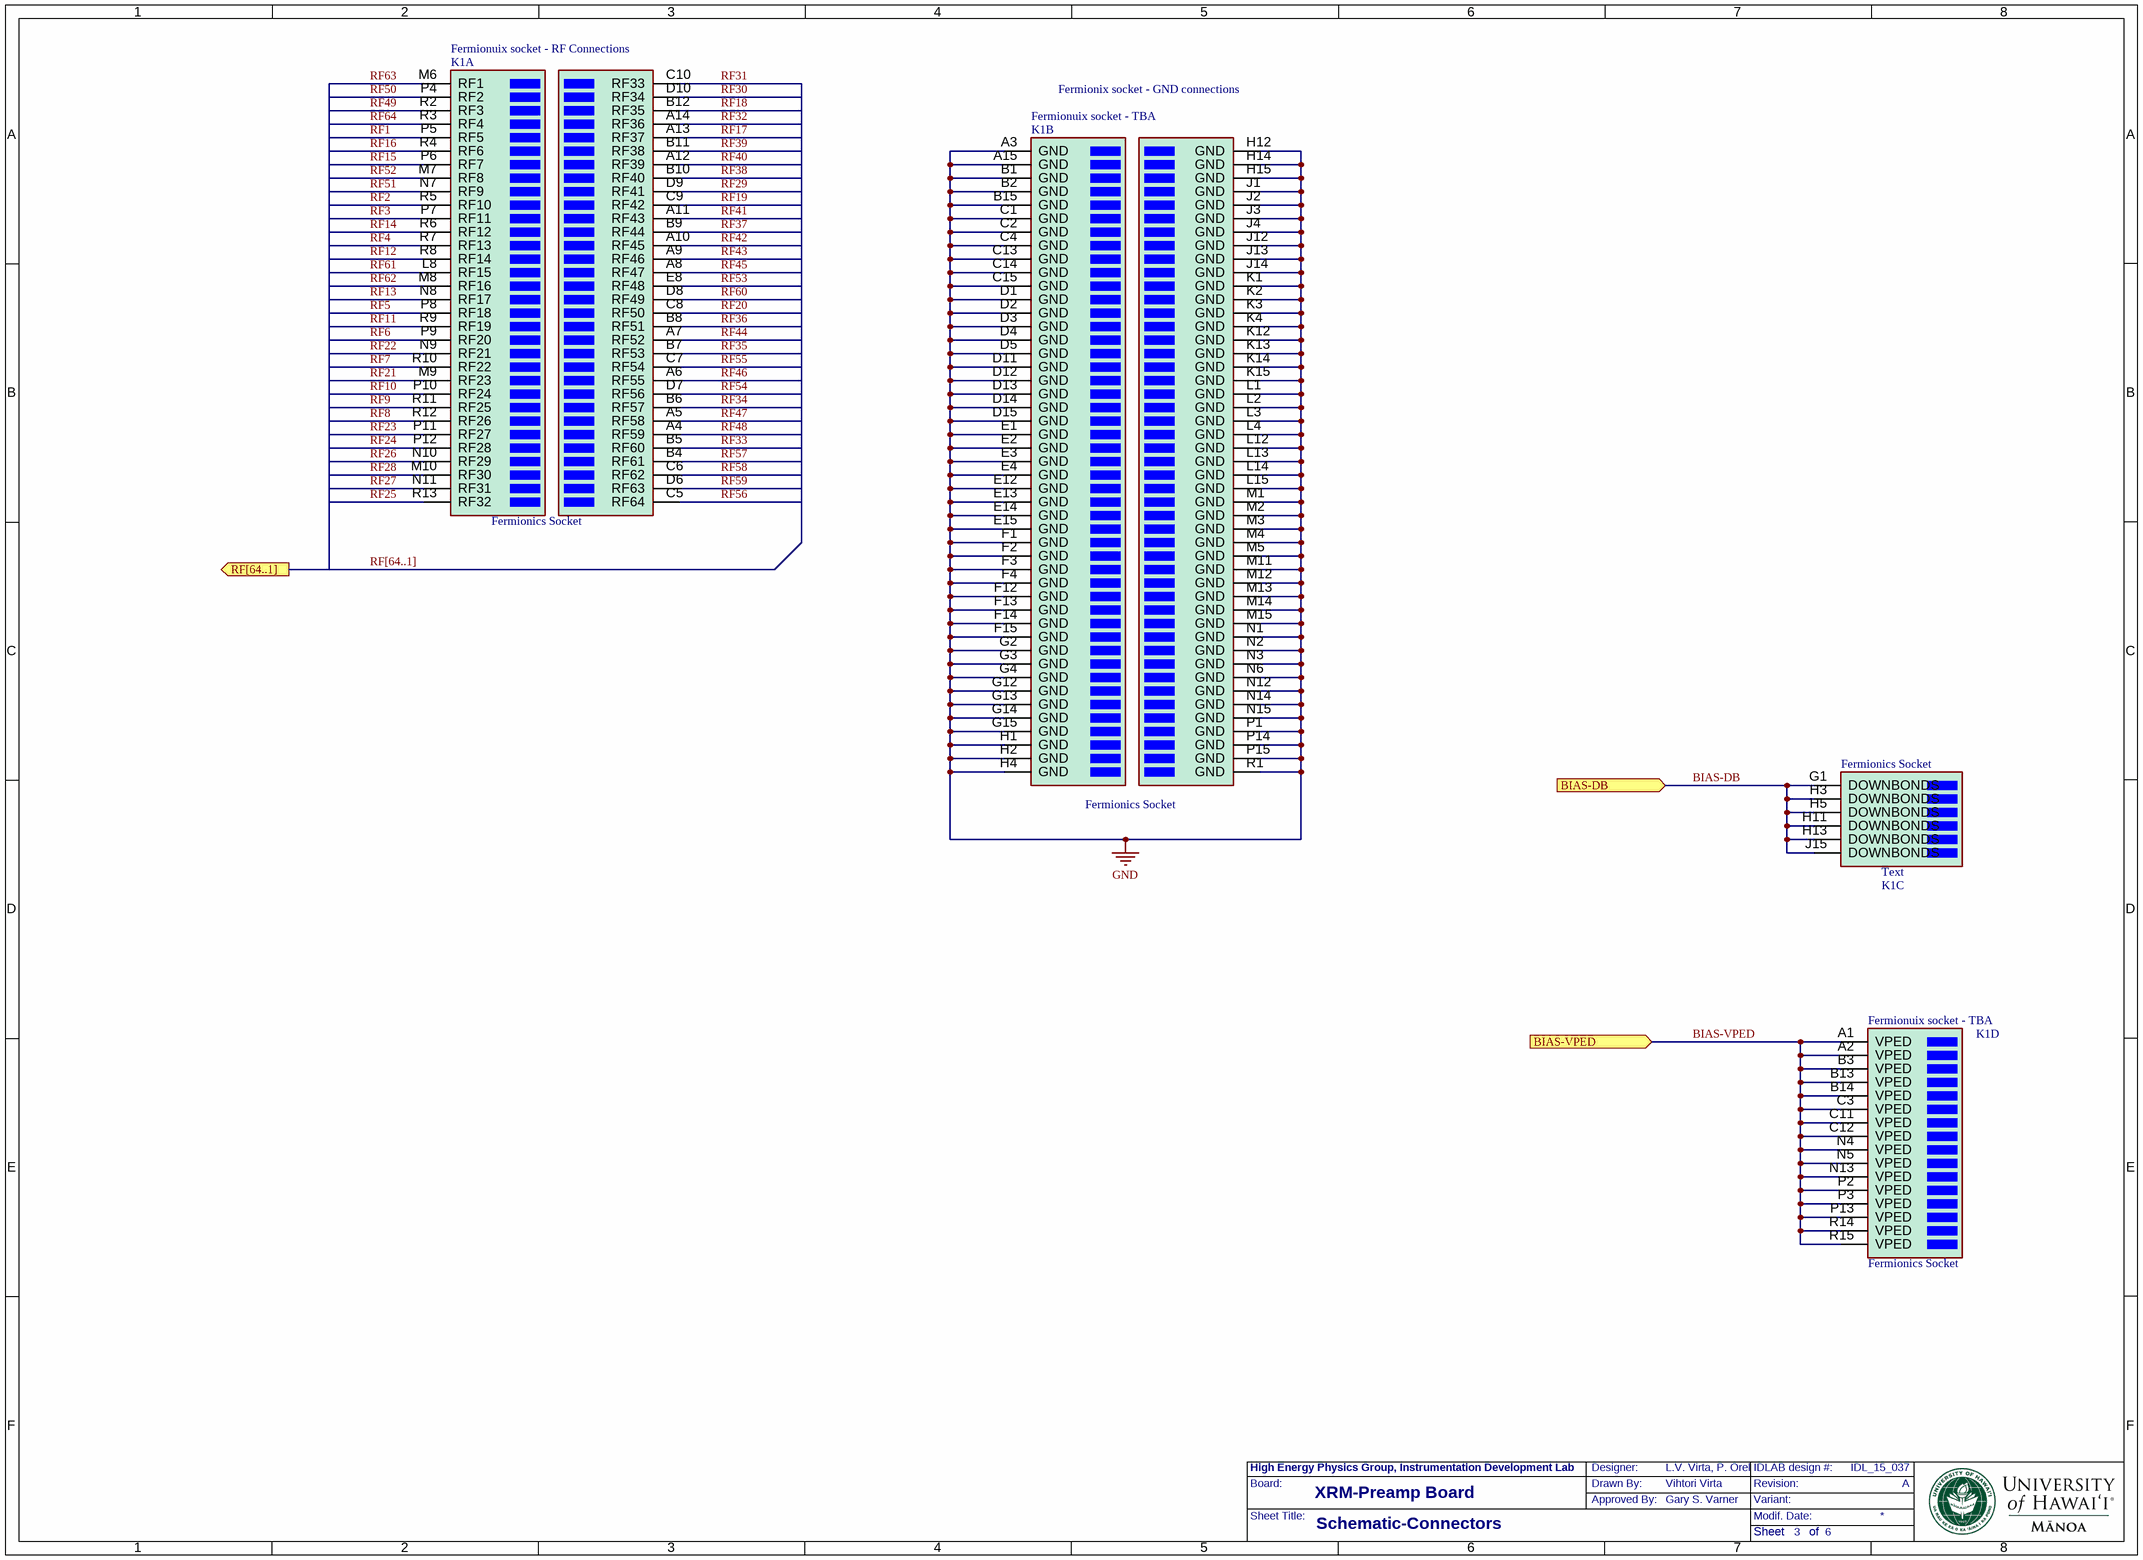
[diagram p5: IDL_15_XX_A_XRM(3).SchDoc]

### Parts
K1  Fermionics Socket  [Fermionics Socket 225v2]  (parts A,B,C,D of 4)

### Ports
BIAS-DB (in), BIAS-VPED (in), RF[64..1] (out)

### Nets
GND: K1.A3(GND) K1.A15(GND) K1.B1(GND) K1.B2(GND) K1.B15(GND) K1.C1(GND) K1.C2(GND) K1.C4(GND) K1.C13(GND) K1.C14(GND) K1.C15(GND) K1.D1(GND) K1.D2(GND) K1.D3(GND) K1.D4(GND) K1.D5(GND) K1.D11(GND) K1.D12(GND) K1.D13(GND) K1.D14(GND) K1.D15(GND) K1.E1(GND) K1.E2(GND) K1.E3(GND) K1.E4(GND) K1.E12(GND) K1.E13(GND) K1.E14(GND) K1.E15(GND) K1.F1(GND) K1.F2(GND) K1.F3(GND) K1.F4(GND) K1.F12(GND) K1.F13(GND) K1.F14(GND) K1.F15(GND) K1.G2(GND) K1.G3(GND) K1.G4(GND) K1.G12(GND) K1.G13(GND) K1.G14(GND) K1.G15(GND) K1.H1(GND) K1.H2(GND) K1.H4(GND) K1.H12(GND) K1.H14(GND) K1.H15(GND) K1.J1(GND) K1.J2(GND) K1.J3(GND) K1.J4(GND) K1.J12(GND) K1.J13(GND) K1.J14(GND) K1.K1(GND) K1.K2(GND) K1.K3(GND) K1.K4(GND) K1.K12(GND) K1.K13(GND) K1.K14(GND) K1.K15(GND) K1.L1(GND) K1.L2(GND) K1.L3(GND) K1.L4(GND) K1.L12(GND) K1.L13(GND) K1.L14(GND) K1.L15(GND) K1.M1(GND) K1.M2(GND) K1.M3(GND) K1.M4(GND) K1.M5(GND) K1.M11(GND) K1.M12(GND) K1.M13(GND) K1.M14(GND) K1.M15(GND) K1.N1(GND) K1.N2(GND) K1.N3(GND) K1.N6(GND) K1.N12(GND) K1.N14(GND) K1.N15(GND) K1.P1(GND) K1.P14(GND) K1.P15(GND) K1.R1(GND)
BIAS-DB: K1.G1(DOWNBONDS) K1.H3(DOWNBONDS) K1.H5(DOWNBONDS) K1.H11(DOWNBONDS) K1.H13(DOWNBONDS) K1.J15(DOWNBONDS) ; port BIAS-DB
BIAS-VPED: K1.A1(VPED) K1.A2(VPED) K1.B3(VPED) K1.B13(VPED) K1.B14(VPED) K1.C3(VPED) K1.C11(VPED) K1.C12(VPED) K1.N4(VPED) K1.N5(VPED) K1.N13(VPED) K1.P2(VPED) K1.P3(VPED) K1.P13(VPED) K1.R14(VPED) K1.R15(VPED) ; port BIAS-VPED  [project net BIAS-DB]
RF1: K1.P5(RF5)
RF2: K1.R5(RF10)
RF3: K1.P7(RF11)
RF4: K1.R7(RF13)
RF5: K1.P8(RF18)
RF6: K1.P9(RF20)
RF7: K1.R10(RF22)
RF8: K1.R12(RF26)
RF9: K1.R11(RF25)
RF10: K1.P10(RF24)
RF11: K1.R9(RF19)
RF12: K1.R8(RF14)
RF13: K1.N8(RF17)
RF14: K1.R6(RF12)
RF15: K1.P6(RF7)
RF16: K1.R4(RF6)
RF17: K1.A13(RF37)
RF18: K1.B12(RF35)
RF19: K1.C9(RF42)
RF20: K1.C8(RF50)
RF21: K1.M9(RF23)
RF22: K1.N9(RF21)
RF23: K1.P11(RF27)
RF24: K1.P12(RF28)
RF25: K1.R13(RF32)
RF26: K1.N10(RF29)
RF27: K1.N11(RF31)
RF28: K1.M10(RF30)
RF29: K1.D9(RF41)
RF30: K1.D10(RF34)
RF31: K1.C10(RF33)
RF32: K1.A14(RF36)
RF33: K1.B5(RF60)
RF34: K1.B6(RF57)
RF35: K1.B7(RF53)
RF36: K1.B8(RF51)
RF37: K1.B9(RF44)
RF38: K1.B10(RF40)
RF39: K1.B11(RF38)
RF40: K1.A12(RF39)
RF41: K1.A11(RF43)
RF42: K1.A10(RF45)
RF43: K1.A9(RF46)
RF44: K1.A7(RF52)
RF45: K1.A8(RF47)
RF46: K1.A6(RF55)
RF47: K1.A5(RF58)
RF48: K1.A4(RF59)
RF49: K1.R2(RF3)
RF50: K1.P4(RF2)
RF51: K1.N7(RF9)
RF52: K1.M7(RF8)
RF53: K1.E8(RF48)
RF54: K1.D7(RF56)
RF55: K1.C7(RF54)
RF56: K1.C5(RF64)
RF57: K1.B4(RF61)
RF58: K1.C6(RF62)
RF59: K1.D6(RF63)
RF60: K1.D8(RF49)
RF61: K1.L8(RF15)
RF62: K1.M8(RF16)
RF63: K1.M6(RF1)
RF64: K1.R3(RF4)

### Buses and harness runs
bus RF[64..1] = port RF[64..1]

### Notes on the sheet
- (near K1) Fermionuix socket - RF Connections
- Fermionix socket - GND connections
- (near K1) Fermionuix socket - TBA
- (near K1) Text

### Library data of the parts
K1 = CN_Fermionics: Fermionics Socket PGA15x15; Manufacturer No: A315-ND; Manufacturer: Aries Electronics; Tech: THDW

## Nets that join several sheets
3V3: IDL_15_XX_A_XRM-TOP(1) (29 pins), A1 (A1_C1.1 A1_C2.1 A1_C3.1 A1_L1.2), A2 (A2_C1.1 A2_C2.1 A2_C3.1 A2_L1.2), A3 (A3_C1.1 A3_C2.1 A3_C3.1 A3_L1.2), A4 (A4_C1.1 A4_C2.1 A4_C3.1 A4_L1.2), A5 (A5_C1.1 A5_C2.1 A5_C3.1 A5_L1.2), A6 (A6_C1.1 A6_C2.1 A6_C3.1 A6_L1.2), A7 (A7_C1.1 A7_C2.1 A7_C3.1 A7_L1.2), A8 (A8_C1.1 A8_C2.1 A8_C3.1 A8_L1.2), A9 (A9_C1.1 A9_C2.1 A9_C3.1 A9_L1.2), A10 (A10_C1.1 A10_C2.1 A10_C3.1 A10_L1.2), A11 (A11_C1.1 A11_C2.1 A11_C3.1 A11_L1.2), A12 (A12_C1.1 A12_C2.1 A12_C3.1 A12_L1.2), A13 (A13_C1.1 A13_C2.1 A13_C3.1 A13_L1.2), A14 (A14_C1.1 A14_C2.1 A14_C3.1 A14_L1.2), A15 (A15_C1.1 A15_C2.1 A15_C3.1 A15_L1.2), A16 (A16_C1.1 A16_C2.1 A16_C3.1 A16_L1.2), A17 (A17_C1.1 A17_C2.1 A17_C3.1 A17_L1.2), A18 (A18_C1.1 A18_C2.1 A18_C3.1 A18_L1.2), A19 (A19_C1.1 A19_C2.1 A19_C3.1 A19_L1.2), A20 (A20_C1.1 A20_C2.1 A20_C3.1 A20_L1.2), A21 (A21_C1.1 A21_C2.1 A21_C3.1 A21_L1.2), A22 (A22_C1.1 A22_C2.1 A22_C3.1 A22_L1.2), A23 (A23_C1.1 A23_C2.1 A23_C3.1 A23_L1.2), A24 (A24_C1.1 A24_C2.1 A24_C3.1 A24_L1.2), A25 (A25_C1.1 A25_C2.1 A25_C3.1 A25_L1.2), A26 (A26_C1.1 A26_C2.1 A26_C3.1 A26_L1.2), A27 (A27_C1.1 A27_C2.1 A27_C3.1 A27_L1.2), A28 (A28_C1.1 A28_C2.1 A28_C3.1 A28_L1.2), A29 (A29_C1.1 A29_C2.1 A29_C3.1 A29_L1.2), A30 (A30_C1.1 A30_C2.1 A30_C3.1 A30_L1.2), A31 (A31_C1.1 A31_C2.1 A31_C3.1 A31_L1.2), A32 (A32_C1.1 A32_C2.1 A32_C3.1 A32_L1.2), A33 (A33_C1.1 A33_C2.1 A33_C3.1 A33_L1.2), A34 (A34_C1.1 A34_C2.1 A34_C3.1 A34_L1.2), A35 (A35_C1.1 A35_C2.1 A35_C3.1 A35_L1.2), A36 (A36_C1.1 A36_C2.1 A36_C3.1 A36_L1.2), A37 (A37_C1.1 A37_C2.1 A37_C3.1 A37_L1.2), A38 (A38_C1.1 A38_C2.1 A38_C3.1 A38_L1.2), A39 (A39_C1.1 A39_C2.1 A39_C3.1 A39_L1.2), A40 (A40_C1.1 A40_C2.1 A40_C3.1 A40_L1.2), A41 (A41_C1.1 A41_C2.1 A41_C3.1 A41_L1.2), A42 (A42_C1.1 A42_C2.1 A42_C3.1 A42_L1.2), A43 (A43_C1.1 A43_C2.1 A43_C3.1 A43_L1.2), A44 (A44_C1.1 A44_C2.1 A44_C3.1 A44_L1.2), A45 (A45_C1.1 A45_C2.1 A45_C3.1 A45_L1.2), A46 (A46_C1.1 A46_C2.1 A46_C3.1 A46_L1.2), A47 (A47_C1.1 A47_C2.1 A47_C3.1 A47_L1.2), A48 (A48_C1.1 A48_C2.1 A48_C3.1 A48_L1.2), A49 (A49_C1.1 A49_C2.1 A49_C3.1 A49_L1.2), A50 (A50_C1.1 A50_C2.1 A50_C3.1 A50_L1.2), A51 (A51_C1.1 A51_C2.1 A51_C3.1 A51_L1.2), A52 (A52_C1.1 A52_C2.1 A52_C3.1 A52_L1.2), A53 (A53_C1.1 A53_C2.1 A53_C3.1 A53_L1.2), A54 (A54_C1.1 A54_C2.1 A54_C3.1 A54_L1.2), A55 (A55_C1.1 A55_C2.1 A55_C3.1 A55_L1.2), A56 (A56_C1.1 A56_C2.1 A56_C3.1 A56_L1.2), A57 (A57_C1.1 A57_C2.1 A57_C3.1 A57_L1.2), A58 (A58_C1.1 A58_C2.1 A58_C3.1 A58_L1.2), A59 (A59_C1.1 A59_C2.1 A59_C3.1 A59_L1.2), A60 (A60_C1.1 A60_C2.1 A60_C3.1 A60_L1.2), A61 (A61_C1.1 A61_C2.1 A61_C3.1 A61_L1.2), A62 (A62_C1.1 A62_C2.1 A62_C3.1 A62_L1.2), A63 (A63_C1.1 A63_C2.1 A63_C3.1 A63_L1.2), A64 (A64_C1.1 A64_C2.1 A64_C3.1 A64_L1.2)
GND: IDL_15_XX_A_XRM-TOP(1) (29 pins), A1 (6 pins), A2 (6 pins), A3 (6 pins), A4 (6 pins), A5 (6 pins), A6 (6 pins), A7 (6 pins), A8 (6 pins), A9 (6 pins), A10 (6 pins), A11 (6 pins), A12 (6 pins), A13 (6 pins), A14 (6 pins), A15 (6 pins), A16 (6 pins), A17 (6 pins), A18 (6 pins), A19 (6 pins), A20 (6 pins), A21 (6 pins), A22 (6 pins), A23 (6 pins), A24 (6 pins), A25 (6 pins), A26 (6 pins), A27 (6 pins), A28 (6 pins), A29 (6 pins), A30 (6 pins), A31 (6 pins), A32 (6 pins), A33 (6 pins), A34 (6 pins), A35 (6 pins), A36 (6 pins), A37 (6 pins), A38 (6 pins), A39 (6 pins), A40 (6 pins), A41 (6 pins), A42 (6 pins), A43 (6 pins), A44 (6 pins), A45 (6 pins), A46 (6 pins), A47 (6 pins), A48 (6 pins), A49 (6 pins), A50 (6 pins), A51 (6 pins), A52 (6 pins), A53 (6 pins), A54 (6 pins), A55 (6 pins), A56 (6 pins), A57 (6 pins), A58 (6 pins), A59 (6 pins), A60 (6 pins), A61 (6 pins), A62 (6 pins), A63 (6 pins), A64 (6 pins), IDL_15_XX_A_XRM-20_PIN_CONNECTOR (12 pins), IDL_15_XX_A_XRM(3) (94 pins)
BIAS-DB: IDL_15_XX_A_XRM-20_PIN_CONNECTOR (CONN1.10 CONN2.10 CONN3.10 CONN4.10), IDL_15_XX_A_XRM(3) (6 pins)
BIAS-DB: IDL_15_XX_A_XRM-20_PIN_CONNECTOR (CONN1.11 CONN2.11 CONN3.11 CONN4.11), IDL_15_XX_A_XRM(3) (16 pins)
RF1: A1 (A1_Cin_1.1 A1_Rin_1.2), IDL_15_XX_A_XRM(3) (K1.P5)
RF2: A2 (A2_Cin_1.1 A2_Rin_1.2), IDL_15_XX_A_XRM(3) (K1.R5)
RF3: A3 (A3_Cin_1.1 A3_Rin_1.2), IDL_15_XX_A_XRM(3) (K1.P7)
RF4: A4 (A4_Cin_1.1 A4_Rin_1.2), IDL_15_XX_A_XRM(3) (K1.R7)
RF5: A5 (A5_Cin_1.1 A5_Rin_1.2), IDL_15_XX_A_XRM(3) (K1.P8)
RF6: A6 (A6_Cin_1.1 A6_Rin_1.2), IDL_15_XX_A_XRM(3) (K1.P9)
RF7: A7 (A7_Cin_1.1 A7_Rin_1.2), IDL_15_XX_A_XRM(3) (K1.R10)
RF8: A8 (A8_Cin_1.1 A8_Rin_1.2), IDL_15_XX_A_XRM(3) (K1.R12)
RF9: A9 (A9_Cin_1.1 A9_Rin_1.2), IDL_15_XX_A_XRM(3) (K1.R11)
RF10: A10 (A10_Cin_1.1 A10_Rin_1.2), IDL_15_XX_A_XRM(3) (K1.P10)
RF11: A11 (A11_Cin_1.1 A11_Rin_1.2), IDL_15_XX_A_XRM(3) (K1.R9)
RF12: A12 (A12_Cin_1.1 A12_Rin_1.2), IDL_15_XX_A_XRM(3) (K1.R8)
RF13: A13 (A13_Cin_1.1 A13_Rin_1.2), IDL_15_XX_A_XRM(3) (K1.N8)
RF14: A14 (A14_Cin_1.1 A14_Rin_1.2), IDL_15_XX_A_XRM(3) (K1.R6)
RF15: A15 (A15_Cin_1.1 A15_Rin_1.2), IDL_15_XX_A_XRM(3) (K1.P6)
RF16: A16 (A16_Cin_1.1 A16_Rin_1.2), IDL_15_XX_A_XRM(3) (K1.R4)
RF17: A17 (A17_Cin_1.1 A17_Rin_1.2), IDL_15_XX_A_XRM(3) (K1.A13)
RF18: A18 (A18_Cin_1.1 A18_Rin_1.2), IDL_15_XX_A_XRM(3) (K1.B12)
RF19: A19 (A19_Cin_1.1 A19_Rin_1.2), IDL_15_XX_A_XRM(3) (K1.C9)
RF20: A20 (A20_Cin_1.1 A20_Rin_1.2), IDL_15_XX_A_XRM(3) (K1.C8)
RF21: A21 (A21_Cin_1.1 A21_Rin_1.2), IDL_15_XX_A_XRM(3) (K1.M9)
RF22: A22 (A22_Cin_1.1 A22_Rin_1.2), IDL_15_XX_A_XRM(3) (K1.N9)
RF23: A23 (A23_Cin_1.1 A23_Rin_1.2), IDL_15_XX_A_XRM(3) (K1.P11)
RF24: A24 (A24_Cin_1.1 A24_Rin_1.2), IDL_15_XX_A_XRM(3) (K1.P12)
RF25: A25 (A25_Cin_1.1 A25_Rin_1.2), IDL_15_XX_A_XRM(3) (K1.R13)
RF26: A26 (A26_Cin_1.1 A26_Rin_1.2), IDL_15_XX_A_XRM(3) (K1.N10)
RF27: A27 (A27_Cin_1.1 A27_Rin_1.2), IDL_15_XX_A_XRM(3) (K1.N11)
RF28: A28 (A28_Cin_1.1 A28_Rin_1.2), IDL_15_XX_A_XRM(3) (K1.M10)
RF29: A29 (A29_Cin_1.1 A29_Rin_1.2), IDL_15_XX_A_XRM(3) (K1.D9)
RF30: A30 (A30_Cin_1.1 A30_Rin_1.2), IDL_15_XX_A_XRM(3) (K1.D10)
RF31: A31 (A31_Cin_1.1 A31_Rin_1.2), IDL_15_XX_A_XRM(3) (K1.C10)
RF32: A32 (A32_Cin_1.1 A32_Rin_1.2), IDL_15_XX_A_XRM(3) (K1.A14)
RF33: A33 (A33_Cin_1.1 A33_Rin_1.2), IDL_15_XX_A_XRM(3) (K1.B5)
RF34: A34 (A34_Cin_1.1 A34_Rin_1.2), IDL_15_XX_A_XRM(3) (K1.B6)
RF35: A35 (A35_Cin_1.1 A35_Rin_1.2), IDL_15_XX_A_XRM(3) (K1.B7)
RF36: A36 (A36_Cin_1.1 A36_Rin_1.2), IDL_15_XX_A_XRM(3) (K1.B8)
RF37: A37 (A37_Cin_1.1 A37_Rin_1.2), IDL_15_XX_A_XRM(3) (K1.B9)
RF38: A38 (A38_Cin_1.1 A38_Rin_1.2), IDL_15_XX_A_XRM(3) (K1.B10)
RF39: A39 (A39_Cin_1.1 A39_Rin_1.2), IDL_15_XX_A_XRM(3) (K1.B11)
RF40: A40 (A40_Cin_1.1 A40_Rin_1.2), IDL_15_XX_A_XRM(3) (K1.A12)
RF41: A41 (A41_Cin_1.1 A41_Rin_1.2), IDL_15_XX_A_XRM(3) (K1.A11)
RF42: A42 (A42_Cin_1.1 A42_Rin_1.2), IDL_15_XX_A_XRM(3) (K1.A10)
RF43: A43 (A43_Cin_1.1 A43_Rin_1.2), IDL_15_XX_A_XRM(3) (K1.A9)
RF44: A44 (A44_Cin_1.1 A44_Rin_1.2), IDL_15_XX_A_XRM(3) (K1.A7)
RF45: A45 (A45_Cin_1.1 A45_Rin_1.2), IDL_15_XX_A_XRM(3) (K1.A8)
RF46: A46 (A46_Cin_1.1 A46_Rin_1.2), IDL_15_XX_A_XRM(3) (K1.A6)
RF47: A47 (A47_Cin_1.1 A47_Rin_1.2), IDL_15_XX_A_XRM(3) (K1.A5)
RF48: A48 (A48_Cin_1.1 A48_Rin_1.2), IDL_15_XX_A_XRM(3) (K1.A4)
RF49: A49 (A49_Cin_1.1 A49_Rin_1.2), IDL_15_XX_A_XRM(3) (K1.R2)
RF50: A50 (A50_Cin_1.1 A50_Rin_1.2), IDL_15_XX_A_XRM(3) (K1.P4)
RF51: A51 (A51_Cin_1.1 A51_Rin_1.2), IDL_15_XX_A_XRM(3) (K1.N7)
RF52: A52 (A52_Cin_1.1 A52_Rin_1.2), IDL_15_XX_A_XRM(3) (K1.M7)
RF53: A53 (A53_Cin_1.1 A53_Rin_1.2), IDL_15_XX_A_XRM(3) (K1.E8)
RF54: A54 (A54_Cin_1.1 A54_Rin_1.2), IDL_15_XX_A_XRM(3) (K1.D7)
RF55: A55 (A55_Cin_1.1 A55_Rin_1.2), IDL_15_XX_A_XRM(3) (K1.C7)
RF56: A56 (A56_Cin_1.1 A56_Rin_1.2), IDL_15_XX_A_XRM(3) (K1.C5)
RF57: A57 (A57_Cin_1.1 A57_Rin_1.2), IDL_15_XX_A_XRM(3) (K1.B4)
RF58: A58 (A58_Cin_1.1 A58_Rin_1.2), IDL_15_XX_A_XRM(3) (K1.C6)
RF59: A59 (A59_Cin_1.1 A59_Rin_1.2), IDL_15_XX_A_XRM(3) (K1.D6)
RF60: A60 (A60_Cin_1.1 A60_Rin_1.2), IDL_15_XX_A_XRM(3) (K1.D8)
RF61: A61 (A61_Cin_1.1 A61_Rin_1.2), IDL_15_XX_A_XRM(3) (K1.L8)
RF62: A62 (A62_Cin_1.1 A62_Rin_1.2), IDL_15_XX_A_XRM(3) (K1.M8)
RF63: A63 (A63_Cin_1.1 A63_Rin_1.2), IDL_15_XX_A_XRM(3) (K1.M6)
RF64: A64 (A64_Cin_1.1 A64_Rin_1.2), IDL_15_XX_A_XRM(3) (K1.R3)
RF-OUT1: A1 (A1_L2.2), IDL_15_XX_A_XRM-20_PIN_CONNECTOR (CONN3.13)
RF-OUT2: A2 (A2_L2.2), IDL_15_XX_A_XRM-20_PIN_CONNECTOR (CONN3.15)
RF-OUT3: A3 (A3_L2.2), IDL_15_XX_A_XRM-20_PIN_CONNECTOR (CONN3.17)
RF-OUT4: A4 (A4_L2.2), IDL_15_XX_A_XRM-20_PIN_CONNECTOR (CONN3.19)
RF-OUT5: A5 (A5_L2.2), IDL_15_XX_A_XRM-20_PIN_CONNECTOR (CONN4.1)
RF-OUT6: A6 (A6_L2.2), IDL_15_XX_A_XRM-20_PIN_CONNECTOR (CONN4.3)
RF-OUT7: A7 (A7_L2.2), IDL_15_XX_A_XRM-20_PIN_CONNECTOR (CONN4.5)
RF-OUT8: A8 (A8_L2.2), IDL_15_XX_A_XRM-20_PIN_CONNECTOR (CONN4.7)
RF-OUT9: A9 (A9_L2.2), IDL_15_XX_A_XRM-20_PIN_CONNECTOR (CONN4.8)
RF-OUT10: A10 (A10_L2.2), IDL_15_XX_A_XRM-20_PIN_CONNECTOR (CONN4.6)
RF-OUT11: A11 (A11_L2.2), IDL_15_XX_A_XRM-20_PIN_CONNECTOR (CONN4.4)
RF-OUT12: A12 (A12_L2.2), IDL_15_XX_A_XRM-20_PIN_CONNECTOR (CONN4.2)
RF-OUT13: A13 (A13_L2.2), IDL_15_XX_A_XRM-20_PIN_CONNECTOR (CONN3.20)
RF-OUT14: A14 (A14_L2.2), IDL_15_XX_A_XRM-20_PIN_CONNECTOR (CONN3.18)
RF-OUT15: A15 (A15_L2.2), IDL_15_XX_A_XRM-20_PIN_CONNECTOR (CONN3.16)
RF-OUT16: A16 (A16_L2.2), IDL_15_XX_A_XRM-20_PIN_CONNECTOR (CONN3.14)
RF-OUT17: A17 (A17_L2.2), IDL_15_XX_A_XRM-20_PIN_CONNECTOR (CONN1.8)
RF-OUT18: A18 (A18_L2.2), IDL_15_XX_A_XRM-20_PIN_CONNECTOR (CONN1.6)
RF-OUT19: A19 (A19_L2.2), IDL_15_XX_A_XRM-20_PIN_CONNECTOR (CONN1.4)
RF-OUT20: A20 (A20_L2.2), IDL_15_XX_A_XRM-20_PIN_CONNECTOR (CONN1.2)
RF-OUT21: A21 (A21_L2.2), IDL_15_XX_A_XRM-20_PIN_CONNECTOR (CONN4.20)
RF-OUT22: A22 (A22_L2.2), IDL_15_XX_A_XRM-20_PIN_CONNECTOR (CONN4.18)
RF-OUT23: A23 (A23_L2.2), IDL_15_XX_A_XRM-20_PIN_CONNECTOR (CONN4.16)
RF-OUT24: A24 (A24_L2.2), IDL_15_XX_A_XRM-20_PIN_CONNECTOR (CONN4.14)
RF-OUT25: A25 (A25_L2.2), IDL_15_XX_A_XRM-20_PIN_CONNECTOR (CONN4.13)
RF-OUT26: A26 (A26_L2.2), IDL_15_XX_A_XRM-20_PIN_CONNECTOR (CONN4.15)
RF-OUT27: A27 (A27_L2.2), IDL_15_XX_A_XRM-20_PIN_CONNECTOR (CONN4.17)
RF-OUT28: A28 (A28_L2.2), IDL_15_XX_A_XRM-20_PIN_CONNECTOR (CONN4.19)
RF-OUT29: A29 (A29_L2.2), IDL_15_XX_A_XRM-20_PIN_CONNECTOR (CONN1.1)
RF-OUT30: A30 (A30_L2.2), IDL_15_XX_A_XRM-20_PIN_CONNECTOR (CONN1.3)
RF-OUT31: A31 (A31_L2.2), IDL_15_XX_A_XRM-20_PIN_CONNECTOR (CONN1.5)
RF-OUT32: A32 (A32_L2.2), IDL_15_XX_A_XRM-20_PIN_CONNECTOR (CONN1.7)
RF-OUT33: A33 (A33_L2.2), IDL_15_XX_A_XRM-20_PIN_CONNECTOR (CONN2.8)
RF-OUT34: A34 (A34_L2.2), IDL_15_XX_A_XRM-20_PIN_CONNECTOR (CONN2.6)
RF-OUT35: A35 (A35_L2.2), IDL_15_XX_A_XRM-20_PIN_CONNECTOR (CONN2.4)
RF-OUT36: A36 (A36_L2.2), IDL_15_XX_A_XRM-20_PIN_CONNECTOR (CONN2.2)
RF-OUT37: A37 (A37_L2.2), IDL_15_XX_A_XRM-20_PIN_CONNECTOR (CONN1.20)
RF-OUT38: A38 (A38_L2.2), IDL_15_XX_A_XRM-20_PIN_CONNECTOR (CONN1.18)
RF-OUT39: A39 (A39_L2.2), IDL_15_XX_A_XRM-20_PIN_CONNECTOR (CONN1.16)
RF-OUT40: A40 (A40_L2.2), IDL_15_XX_A_XRM-20_PIN_CONNECTOR (CONN1.14)
RF-OUT41: A41 (A41_L2.2), IDL_15_XX_A_XRM-20_PIN_CONNECTOR (CONN1.13)
RF-OUT42: A42 (A42_L2.2), IDL_15_XX_A_XRM-20_PIN_CONNECTOR (CONN1.15)
RF-OUT43: A43 (A43_L2.2), IDL_15_XX_A_XRM-20_PIN_CONNECTOR (CONN1.17)
RF-OUT44: A44 (A44_L2.2), IDL_15_XX_A_XRM-20_PIN_CONNECTOR (CONN2.1)
RF-OUT45: A45 (A45_L2.2), IDL_15_XX_A_XRM-20_PIN_CONNECTOR (CONN1.19)
RF-OUT46: A46 (A46_L2.2), IDL_15_XX_A_XRM-20_PIN_CONNECTOR (CONN2.3)
RF-OUT47: A47 (A47_L2.2), IDL_15_XX_A_XRM-20_PIN_CONNECTOR (CONN2.5)
RF-OUT48: A48 (A48_L2.2), IDL_15_XX_A_XRM-20_PIN_CONNECTOR (CONN2.7)
RF-OUT49: A49 (A49_L2.2), IDL_15_XX_A_XRM-20_PIN_CONNECTOR (CONN3.8)
RF-OUT50: A50 (A50_L2.2), IDL_15_XX_A_XRM-20_PIN_CONNECTOR (CONN3.6)
RF-OUT51: A51 (A51_L2.2), IDL_15_XX_A_XRM-20_PIN_CONNECTOR (CONN3.4)
RF-OUT52: A52 (A52_L2.2), IDL_15_XX_A_XRM-20_PIN_CONNECTOR (CONN3.2)
RF-OUT53: A53 (A53_L2.2), IDL_15_XX_A_XRM-20_PIN_CONNECTOR (CONN2.20)
RF-OUT54: A54 (A54_L2.2), IDL_15_XX_A_XRM-20_PIN_CONNECTOR (CONN2.18)
RF-OUT55: A55 (A55_L2.2), IDL_15_XX_A_XRM-20_PIN_CONNECTOR (CONN2.16)
RF-OUT56: A56 (A56_L2.2), IDL_15_XX_A_XRM-20_PIN_CONNECTOR (CONN2.14)
RF-OUT57: A57 (A57_L2.2), IDL_15_XX_A_XRM-20_PIN_CONNECTOR (CONN2.13)
RF-OUT58: A58 (A58_L2.2), IDL_15_XX_A_XRM-20_PIN_CONNECTOR (CONN2.15)
RF-OUT59: A59 (A59_L2.2), IDL_15_XX_A_XRM-20_PIN_CONNECTOR (CONN2.17)
RF-OUT60: A60 (A60_L2.2), IDL_15_XX_A_XRM-20_PIN_CONNECTOR (CONN2.19)
RF-OUT61: A61 (A61_L2.2), IDL_15_XX_A_XRM-20_PIN_CONNECTOR (CONN3.1)
RF-OUT62: A62 (A62_L2.2), IDL_15_XX_A_XRM-20_PIN_CONNECTOR (CONN3.3)
RF-OUT63: A63 (A63_L2.2), IDL_15_XX_A_XRM-20_PIN_CONNECTOR (CONN3.5)
RF-OUT64: A64 (A64_L2.2), IDL_15_XX_A_XRM-20_PIN_CONNECTOR (CONN3.7)

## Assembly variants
Single-Ended Input: not fitted C2 C4 C9 C10 C19 C20 C22 C24 C29 C30 C39 C40 C42 C45 C50 C52 C54 C59 C60 C69 C70 C72 C74 C79 C80 C89 C90 C92 C95 C100 C102 C104 C109 C110 C119 C120 C122 C124 C129 C130 C139 C140 C142 C145 C150 HS1 R3 R5 R7 R23 R25 R39 R50 R52 R68 R70 R84 R95 R97 R113 R115 R129 R164 R165 R166 R167 R168 R169 R170 R171 R172 R173 R174 R175 R176 R177 R178 TIP1
Differential Input: not fitted C2 C4 C19 C20 C22 C24 C39 C40 C42 C50 C52 C54 C69 C70 C72 C74 C89 C90 C92 C100 C102 C104 C119 C120 C122 C124 C139 C140 C142 C150 HS1 R4 R5 R7 R13 R14 R21 R22 R23 R25 R31 R32 R38 R39 R48 R49 R50 R52 R58 R59 R66 R67 R68 R70 R76 R77 R83 R84 R88 R93 R94 R95 R97 R103 R104 R111 R112 R113 R115 R121 R122 R128 R129 R133 R164 R333 TIP1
